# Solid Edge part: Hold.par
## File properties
Author: wojci
Template: ISO Metric Part.par
Last saved by: wojci
Revision: 38
Application: Solid Edge
Username: wojci
Accuracy: 0.990
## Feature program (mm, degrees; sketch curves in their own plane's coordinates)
sketch for "unnamed Protrusion 1" plane through (0, 0, 0) normal (0, 0, 1) x-axis (1, 0, 0)
  line (27, 41.0044) -> (27, -16.9956)
  line (27, -16.9956) -> (0, -16.9956)
  line (0, -16.9956) -> (0, 41.0044)
  line (0, 41.0044) -> (27, 41.0044)
extrude "unnamed Protrusion 1" add finite 70 along +normal
sketch for "unnamed Cutout 1" plane through (27, 5.5044, 35) normal (1, 0, 0) x-axis (0, 1, 0)
  line (4.5, 35) -> (4.5, -25)
  line (4.5, -25) -> (27.5, -25)
  line (27.5, -25) -> (27.5, 35)
  line (27.5, 35) -> (4.5, 35)
extrude "unnamed Cutout 1" cut through along -normal
sketch for "unnamed Cutout 2" plane through (27, 12.0044, 35) normal (1, 0, 0) x-axis (0, 1, 0)
  line (-2, 35) -> (-13, 35)
  line (-13, 35) -> (-13, 25)
  line (-13, 25) -> (-26.5, 25)
  line (-26.5, 35) -> (-26.5, 25)
  line (-29, 35) -> (-26.5, 35)
  line (-29, 25) -> (-29, 35)
  line (-29, 25) -> (-40, 25)
  line (-40, 25) -> (-40, -16)
  line (-40, -16) -> (-13, -16)
  line (-13, -25) -> (-13, -16)
  line (-2, -25) -> (-13, -25)
  line (-2, -16) -> (-2, -25)
  line (-2, -16) -> (-2, 25)
  line (-2, 25) -> (-2, 35)
extrude "unnamed Cutout 2" cut finite 21 along -normal
sketch for "Hole_1" plane through (14.5, -0.9956, 65) normal (0, 1, 0) x-axis (-1, 0, 0)
  hole centre (-7, -0.75) bore radius 1.0065
hole "Hole_1" nominal diameter 2.5 finite  ThreadDepth = 2 mm
sketch for "unnamed Hole 1" plane through (14.5, -0.9956, 65) normal (0, 1, 0) x-axis (-1, 0, 0)
  hole centre (3, -0.75) bore radius 1.0065
hole "unnamed Hole 1" finite
sketch for "unnamed Hole 2" plane through (14.5, -0.9956, 65) normal (0, 1, 0) x-axis (-1, 0, 0)
  hole centre (-7, -49.25) bore radius 1.0065
hole "unnamed Hole 2" finite
sketch for "unnamed Hole 3" plane through (14.5, -0.9956, 65) normal (0, 1, 0) x-axis (-1, 0, 0)
  hole centre (3, -49.25) bore radius 1.0065
hole "unnamed Hole 3" finite
pattern "unnamed Pattern 1" of "Hole_1", "unnamed Hole 1", "unnamed Hole 2", "unnamed Hole 3"
sketch for "Hole_5" plane through (12.5, 41.0044, 35) normal (0, 1, 0) x-axis (-1, 0, 0)
  hole centre (-1, -25) bore radius 3
  dimension (linear) = 1
  dimension (linear) = 1
hole "Hole_5" diameter 6 finite
fillet "Round_1" radius 4
sketch for "unnamed RevolvedCutout 1" plane through (12.5, 14.0044, 10) normal (0, 0, 1) x-axis (0, 1, 0)
  line (19, -4) -> (-6, -4)
  line (-6, -4) -> (-11, -1)
  line (-11, -1) -> (19, -1)
  line (19, -4) -> (19, -1)
revolve "unnamed RevolvedCutout 1" cut full turn 360 deg
sketch for "Hole_6" plane through (13.5, 33.0044, 10) normal (0, -1, 0) x-axis (1, 0, 0)
  hole centre (0, 0) bore radius 1.2295
hole "Hole_6" nominal diameter 3 through  ThreadDepth = 2 mm
sketch for "unnamed Cutout 3" plane through (12.5, -16.9956, 35) normal (0, -1, 0) x-axis (1, 0, 0)
  line (7.5, -35) -> (14.5, -30.9585)
  line (14.5, -30.9585) -> (14.5, -35)
  line (14.5, -35) -> (7.5, -35)
extrude "unnamed Cutout 3" cut through along -normal
sketch for "ExtrudedProtrusion_2" plane through (12.5, 41.0044, 35) normal (0, 1, 0) x-axis (-1, 0, 0)
  line (-14.5, -19.25) -> (-14.5, 35)
  line (-14.5, 35) -> (-1, 35)
  line (-1, 35) -> (12.5, 35)
  line (12.5, 35) -> (12.5, -25)
  line (12.5, -25) -> (4.75, -25)
  line (4.75, -25) -> (4.75, -22)
  arc centre (2, -22) radius 2.75 from (4.75, -22) to (2, -19.25) ccw
  line (2, -19.25) -> (-14.5, -19.25)
extrude "ExtrudedProtrusion_2" add finite 10 along +normal
sketch for "ExtrudedProtrusion_8" plane through (10, 12.0044, 0) normal (0, 0, -1) x-axis (-1, 0, 0)
extrude "ExtrudedProtrusion_8" add finite 0.5 along +normal
sketch for "Hole_7" plane through (12.5, 14.0044, 10) normal (0, 0, 1) x-axis (0, 1, 0)
hole "Hole_7" diameter 3 through  CounterBoreDepth = 2.2 mm
sketch for "ExtrudedCutout_4" plane through (0, 17.0044, 35) normal (-1, 0, 0) x-axis (0, -1, 0)
  line (-34, 35) -> (-34, -17)
  line (-34, -17) -> (-26, -12.3812)
  line (-26, -12.3812) -> (-26, 35)
  line (-26, 35) -> (-34, 35)
extrude "ExtrudedCutout_4" cut finite 5 along -normal
sketch for "unnamed RevolvedCutout 2" plane through (0, 17.0044, 35) normal (-1, 0, 0) x-axis (0, -1, 0)
  line (-26.25, -11) -> (-29.5, -11)
  line (-29.5, -11) -> (-29.5, -17)
  line (-29.5, -17) -> (-26.25, -17)
  line (-26.25, -17) -> (-26.25, -11)
revolve "unnamed RevolvedCutout 2" cut full turn 360 deg
sketch for "Hole_8" plane through (1.625, 46.5044, 18) normal (0, 0, 1) x-axis (0, -1, 0)
  hole centre (0, -1.625) bore radius 1.2295
hole "Hole_8" nominal diameter 3 through
sketch for "unnamed Cutout 4" plane through (27, 17.0044, 36.4434) normal (1, 0, 0) x-axis (0, 1, 0)
  line (34, -16.6934) -> (34, 33.5566)
  line (34, 33.5566) -> (26, 33.5566)
  line (26, 33.5566) -> (34, -16.6934)
extrude "unnamed Cutout 4" cut through along -normal
sketch for "ExtrudedProtrusion_3" plane through (12.5, -3.4956, 70) normal (0, 0, 1) x-axis (0, 1, 0)
  line (-11, -14.5) -> (2.5, -14.5)
  line (2.5, -14.5) -> (2.5, 12.5)
  line (2.5, 12.5) -> (-11, 12.5)
  line (-11, 12.5) -> (-11, -14.5)
extrude "ExtrudedProtrusion_3" add finite 2.25 along +normal
sketch for "Hole_9" plane through (27, -7.7456, 66.125) normal (1, 0, 0) x-axis (0, 1, 0)
  line (0, 0) -> (0, 0)
  hole centre (0, 2.125) bore radius 1.2295
hole "Hole_9" nominal diameter 3 finite  ThreadDepth = 2 mm
sketch for "unnamed Hole 4" plane through (27, -7.7456, 66.125) normal (1, 0, 0) x-axis (0, 1, 0)
  hole centre (0, -54.375) bore radius 1.2295
hole "unnamed Hole 4" finite
sketch for "unnamed Hole 5" plane through (27, -7.7456, 66.125) normal (1, 0, 0) x-axis (0, 1, 0)
hole "unnamed Hole 5" finite
sketch for "unnamed Hole 6" plane through (27, -7.7456, 66.125) normal (1, 0, 0) x-axis (0, 1, 0)
  hole centre (45.75, -1.125) bore radius 1.2295
hole "unnamed Hole 6" finite
sketch for "unnamed Hole 7" plane through (27, -7.7456, 66.125) normal (1, 0, 0) x-axis (0, 1, 0)
  hole centre (45.75, -37.375) bore radius 1.2295
hole "unnamed Hole 7" finite
pattern "unnamed Pattern 2" of "Hole_9", "unnamed Hole 4", "unnamed Hole 5", "unnamed Hole 6", "unnamed Hole 7"
sketch for "ExtrudedProtrusion_4" plane through (12.5, 14.0044, 10) normal (0, 0, 1) x-axis (0, 1, 0)
  line (6.75, 6.5) -> (-4, 6.5)
  line (-4, 6.5) -> (-4, 12.5)
  line (-4, 12.5) -> (19, 12.5)
  line (19, 12.5) -> (19, 6.5)
  line (19, 6.5) -> (9.25, 6.5)
extrude "ExtrudedProtrusion_4" add finite 18 along +normal
fillet "Round_2" radius 4
sketch for "ExtrudedCutout_6" #1 plane through (27, -7.7456, 66.125) normal (1, 0, 0) x-axis (0, 1, 0)
  line (4.75, 6.125) -> (4.75, -3.625)
  line (4.75, -3.625) -> (-4.75, -3.625)
  line (-4.75, -3.625) -> (-4.75, 6.125)
  line (-4.75, 6.125) -> (4.75, 6.125)
sketch for "ExtrudedCutout_6" #2 plane through (27, -7.7456, 66.125) normal (1, 0, 0) x-axis (0, 1, 0)
  line (4.75, -61.0835) -> (4.75, -47.125)
  line (4.75, -47.125) -> (-4.75, -47.125)
  line (-4.75, -47.125) -> (-4.75, -61.0835)
  line (-4.75, -61.0835) -> (4.75, -61.0835)
sketch for "ExtrudedCutout_6" #3 plane through (27, -7.7456, 66.125) normal (1, 0, 0) x-axis (0, 1, 0)
  line (42.75, -48.375) -> (48.75, -48.375)
  line (48.75, -48.375) -> (48.75, -33.375)
  line (48.75, -33.375) -> (42.75, -33.375)
  line (42.75, -33.375) -> (42.75, -48.375)
sketch for "ExtrudedCutout_6" #4 plane through (27, -7.7456, 66.125) normal (1, 0, 0) x-axis (0, 1, 0)
  line (42.75, -6.125) -> (48.75, -6.125)
  line (48.75, -6.125) -> (48.75, 3.875)
  line (48.75, 3.875) -> (42.75, 3.875)
  line (42.75, 3.875) -> (42.75, -6.125)
extrude "ExtrudedCutout_6" cut finite 1 along -normal
sketch for "unnamed Cutout 5" plane through (27, 17.0044, 37.1651) normal (1, 0, 0) x-axis (0, 1, 0)
  line (-34, -30.1651) -> (12, -30.1651)
  line (12, -30.1651) -> (12, -28.1651)
  line (12, -28.1651) -> (-34, -28.1651)
  line (-34, -28.1651) -> (-34, -30.1651)
extrude "unnamed Cutout 5" cut finite 2 along -normal
chamfer "Chamfer_2" setback 2
sketch for "ExtrudedProtrusion_6" plane through (17, -8.9956, 19) normal (0, 0, 1) x-axis (0, 1, 0)
extrude "ExtrudedProtrusion_6" add finite 0.5 along +normal
sketch for "ExtrudedCutout_9" plane through (17, -7.7456, 60) normal (0, 0, -1) x-axis (0, 1, 0)
extrude "ExtrudedCutout_9" cut finite 0.5 along -normal
sketch for "unnamed Hole 8" plane through (27.1466, 42.1237, 12.8523) normal (0.129557, 0.989341, -0.066486) x-axis (-0.991534, 0.129844, 0)
  hole centre (0, 0) bore radius 2.2
hole "unnamed Hole 8" through
fillet "Round_4" radius 0.5
sketch used by "ExtrudedCutout_11" plane through (13.5, 33.0044, 42) normal (0, -1, 0) x-axis (-1, 0, 0)
extrude "ExtrudedCutout_11" cut finite 39 along -normal
fillet "Round_6" radius 1.25
sketch used by "unnamed Cutout 6" plane through (0, 14.1397, 36.125) normal (-1, 0, 0) x-axis (0, -1, 0)
extrude "unnamed Cutout 6" cut through along -normal
sketch for "unnamed Hole 9" plane through (13.5141, 33.0044, 42) normal (0, -1, 0) x-axis (1, 0, 0)
hole "unnamed Hole 9" through
sketch for "Hole_18" plane through (13.5141, 43.0044, 42) normal (0, -1, 0) x-axis (1, 0, 0)
  hole centre (2.9859, 8) bore radius 3.75
hole "Hole_18" diameter 7.5 through  Plane_Distance = 10 mm
body pattern "unnamed BodyPattern 1"
pattern "unnamed Pattern 3"
sketch for "ExtrudedCutout_8" #1 plane through (0, -0.9956, 66.125) normal (0, 1, 0) x-axis (-1, 0, 0)
  line (-27, 6.125) -> (-6, 6.125)
  line (-6, 6.125) -> (-6, -5.625)
  line (-6, -5.625) -> (-27, -5.625)
  line (-27, -5.625) -> (-27, 6.125)
sketch for "ExtrudedCutout_8" #2 plane through (0, -0.9956, 66.125) normal (0, 1, 0) x-axis (-1, 0, 0)
  line (-27, -46.625) -> (-6, -46.625)
  line (-6, -46.625) -> (-6, -56.125)
  line (-6, -56.125) -> (-27, -56.125)
  line (-27, -56.125) -> (-27, -46.625)
extrude "ExtrudedCutout_8" cut finite 1 along -normal
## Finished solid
Body 1: solid body, 205 faces, 460 edges, 252 vertices.
  Faces by surface: plane 130, cylinder 65, blend 8, cone 2
  Edges by curve: line 307, circle 110, intersection 24, ellipse 19
Bounding box of the edges (mm; curved faces can reach further): 54.000 x 68.000 x 72.750, from (-27, -16.9956, -0.5) to (27, 51.0044, 72.25).
Cylindrical faces by radius (mm): R1.0065 x16, R1.2295 x28, R1.8 x2, R2.2 x2, R2.5 x2, R2.75 x2, R3 x4, R3.25 x3, R3.75 x2, R4 x3, R19 x1
Conical faces (half-angle, radius in mm at the cone's reference point): 30.9638 deg R3 x2
Planar faces by outward normal: +x 20, +y 30, +z 26, -x 20, -y 15, -z 10, oblique 9
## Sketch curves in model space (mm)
line (11.5, 33.0044, 64.25) -> (0, 33.0044, 64.25)
line (13.5, 33.0044, 72.25) -> (0, 33.0044, 72.25)
line (0, 33.0044, 61.75) -> (0, 33.0044, 72.25)
line (9, 33.0044, 61.75) -> (0, 33.0044, 61.75)
arc centre (9, 33.0044, 64.25) radius 2.5 from (11.4304, 33.0044, 63.6642) through (10.4892, 33.0044, 62.242) to (9, 33.0044, 61.75)
line (11.4304, 33.0044, 63.6642) -> (13.5, 33.0044, 72.25)
line (0, 41.0044, 5) -> (0, -16.9956, 5)
line (0, 41.0044, 10) -> (0, -16.9956, 10)
line (0, 22.0044, -0.5) -> (0, 22.0044, 28)
line (0, 41.0044, -0.5) -> (0, 28.0044, -0.5)
line (0, 41.0044, 5) -> (0, 41.0044, -0.5)
arc centre (0, 41.3779, -13.9963) radius 19 from (0, 41.0044, 5) through (0, 33.9747, 3.502) to (0, 28.0044, -0.5)
line (0, 28.0044, -0.5) -> (0, 28.0044, 28)
line (27, 29.0044, 10) -> (27, 29.0044, 4.0415)
line (27, -16.9956, 7) -> (27, 29.0044, 7)
line (27, 29.0044, 7) -> (27, 29.0044, 9)
line (27, 29.0044, 9) -> (27, -16.9956, 9)
line (27, -16.9956, 9) -> (27, -16.9956, 7)
line (27, -16.9956, 9) -> (27, 41.0044, 9)
line (27, -16.9956, 7) -> (27, 41.0044, 7)
line (27, 41.0044, 70) -> (27, 41.0044, 4.0415)
line (27, 35.0044, 70) -> (27, 35.0044, 4.0415)
line (27, -2.9956, 72.25) -> (27, -2.9956, 4.0415)
line (27, -12.4956, 72.25) -> (27, -12.4956, 4.0415)
line (27, -14.4956, 62.5) -> (27, -0.9956, 62.5)
line (27, 41.0044, 60) -> (27, 41.0044, 70)
line (27, 41.0044, 70) -> (27, 35.0044, 70)
line (27, 35.0044, 70) -> (27, 35.0044, 60)
line (27, 35.0044, 60) -> (27, 41.0044, 60)
line (27, 41.0044, 17.75) -> (27, 41.0044, 32.75)
line (27, 41.0044, 32.75) -> (27, 35.0044, 32.75)
line (27, 35.0044, 32.75) -> (27, 35.0044, 17.75)
line (27, 35.0044, 17.75) -> (27, 41.0044, 17.75)
line (27, -2.9956, 5.0415) -> (27, -2.9956, 19)
line (27, -2.9956, 19) -> (27, -12.4956, 19)
line (27, -12.4956, 19) -> (27, -12.4956, 5.0415)
line (27, -12.4956, 5.0415) -> (27, -2.9956, 5.0415)
line (27, -2.9956, 72.25) -> (27, -2.9956, 62.5)
line (27, -2.9956, 62.5) -> (27, -12.4956, 62.5)
line (27, -12.4956, 62.5) -> (27, -12.4956, 72.25)
line (27, -12.4956, 72.25) -> (27, -2.9956, 72.25)
line (27, 35.0044, 60) -> (27, 41.0044, 60)
line (27, 35.0044, 32.75) -> (27, 41.0044, 32.75)
line (27, 33.0044, 17.75) -> (27, 51.0044, 17.75)
line (27, -16.9956, 5.0415) -> (27, 41.0044, 5.0415)
line (0, 33.0044, 10) -> (6, 33.0044, 10)
line (6, 33.0044, 10) -> (6, 23.2544, 10)
arc centre (9, 22.0044, 10) radius 3.25 from (6, 20.7544, 10) through (5.75, 22.0044, 10) to (6, 23.2544, 10)
line (6, 20.7544, 10) -> (6, 10.0044, 10)
line (6, 10.0044, 10) -> (0, 10.0044, 10)
line (0, 10.0044, 10) -> (0, 33.0044, 10)
line (27, -0.9956, 70) -> (0, -0.9956, 70)
line (0, -0.9956, 70) -> (0, -14.4956, 70)
line (0, -14.4956, 70) -> (27, -14.4956, 70)
line (27, -14.4956, 70) -> (27, -0.9956, 70)
line (27, 33.0044, 19.75) -> (27, 51.0044, 19.75)
line (27, 51.0044, 19.75) -> (27, 51.0044, 70)
line (27, 51.0044, 70) -> (27, 43.0044, 70)
line (27, 43.0044, 70) -> (27, 51.0044, 19.75)
line (27, 43.0044, 70) -> (27, 43.0044, 15.75)
line (0, 46.5044, 10) -> (0, 46.5044, 70)
line (0, 43.2544, 18) -> (0, 43.2544, 24)
line (0, 43.2544, 24) -> (0, 46.5044, 24)
line (0, 46.5044, 24) -> (0, 46.5044, 18)
line (0, 46.5044, 18) -> (0, 43.2544, 18)
line (0, 51.0044, 18) -> (0, 33.0044, 18)
line (0, 43.0044, 22.6188) -> (0, 43.0044, 70)
line (0, 43.0044, 70) -> (0, 51.0044, 70)
line (0, 51.0044, 70) -> (0, 51.0044, 18)
line (0, 51.0044, 18) -> (0, 43.0044, 22.6188)
line (0, 46.5044, 70) -> (0, 46.5044, 10)
line (0, 51.0044, 18) -> (0, 43.0044, 18)
line (0, 43.0044, 70) -> (0, 43.0044, 10)
line (27, 41.0044, 10) -> (0, 41.0044, 10)
line (0, 41.0044, 70) -> (0, 41.0044, 10)
line (0, 41.0044, 10) -> (7.75, 41.0044, 10)
line (7.75, 41.0044, 10) -> (7.75, 41.0044, 13)
arc centre (10.5, 41.0044, 13) radius 2.75 from (7.75, 41.0044, 13) through (8.6128, 41.0044, 15.0003) to (10.5, 41.0044, 15.75)
line (10.5, 41.0044, 15.75) -> (27, 41.0044, 15.75)
line (27, 41.0044, 15.75) -> (27, 41.0044, 70)
line (27, 41.0044, 70) -> (13.5, 41.0044, 70)
line (13.5, 41.0044, 70) -> (0, 41.0044, 70)
line (7.75, 41.0044, 70) -> (7.75, 41.0044, 0)
line (27, -16.9956, 4.0415) -> (27, -16.9956, 0)
line (27, -16.9956, 0) -> (20, -16.9956, 0)
line (20, -16.9956, 0) -> (27, -16.9956, 4.0415)
line (13.5, 41.0044, 10) -> (13.5, -0.9956, 10)
line (16.5, 8.0044, 10) -> (13.5, 3.0044, 10)
line (13.5, 3.0044, 10) -> (13.5, 33.0044, 10)
line (16.5, 33.0044, 10) -> (13.5, 33.0044, 10)
line (16.5, 33.0044, 10) -> (16.5, 8.0044, 10)
line (27, -0.9956, 10) -> (27, -0.9956, 19)
line (27, 10.0044, 10) -> (27, -0.9956, 10)
line (27, 10.0044, 19) -> (27, 10.0044, 10)
line (27, 10.0044, 19) -> (27, 10.0044, 60)
line (27, 10.0044, 60) -> (27, 10.0044, 70)
line (27, 10.0044, 70) -> (27, -0.9956, 70)
line (27, -0.9956, 70) -> (27, -0.9956, 60)
line (27, -0.9956, 60) -> (27, -14.4956, 60)
line (27, -14.4956, 70) -> (27, -14.4956, 60)
line (27, -16.9956, 70) -> (27, -14.4956, 70)
line (27, -16.9956, 60) -> (27, -16.9956, 70)
line (27, -16.9956, 60) -> (27, -27.9956, 60)
line (27, -27.9956, 60) -> (27, -27.9956, 19)
line (27, -27.9956, 19) -> (27, -0.9956, 19)
line (27, 10.0044, 70) -> (27, 10.0044, 10)
line (27, 10.0044, 10) -> (27, 33.0044, 10)
line (27, 33.0044, 10) -> (27, 33.0044, 70)
line (27, 33.0044, 70) -> (27, 10.0044, 70)
line (27, 41.0044, 0) -> (27, -16.9956, 0)
line (27, -16.9956, 0) -> (0, -16.9956, 0)
line (0, -16.9956, 0) -> (0, 41.0044, 0)
line (0, 41.0044, 0) -> (27, 41.0044, 0)
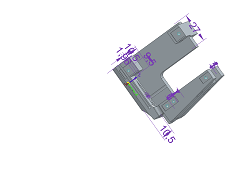
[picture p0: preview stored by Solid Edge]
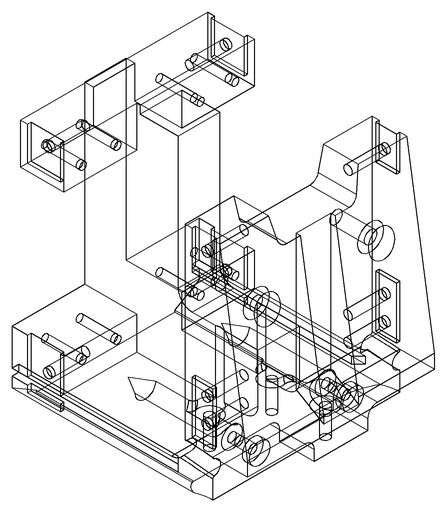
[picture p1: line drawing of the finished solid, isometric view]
